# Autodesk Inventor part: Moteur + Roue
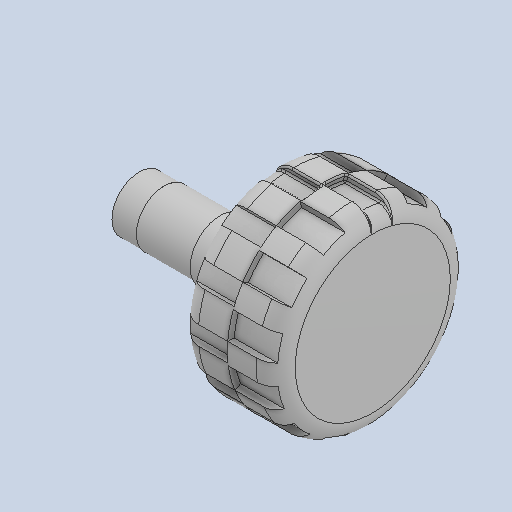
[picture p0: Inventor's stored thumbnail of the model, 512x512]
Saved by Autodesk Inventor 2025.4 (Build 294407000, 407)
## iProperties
Created: 2026-06
Part Number: Moteur + Roue
Material: Generic
Document SubType Name: Modeling
Designer: AdminForWorker
Density: 1 g/cm^3
Appearance: Default
Title: Moteur + Roue v3
Author: AdminForWorker
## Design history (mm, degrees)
feature "Moteur"
feature "Roue"
body "Solid1"
body "Solid2"
